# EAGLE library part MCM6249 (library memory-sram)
MEMORY
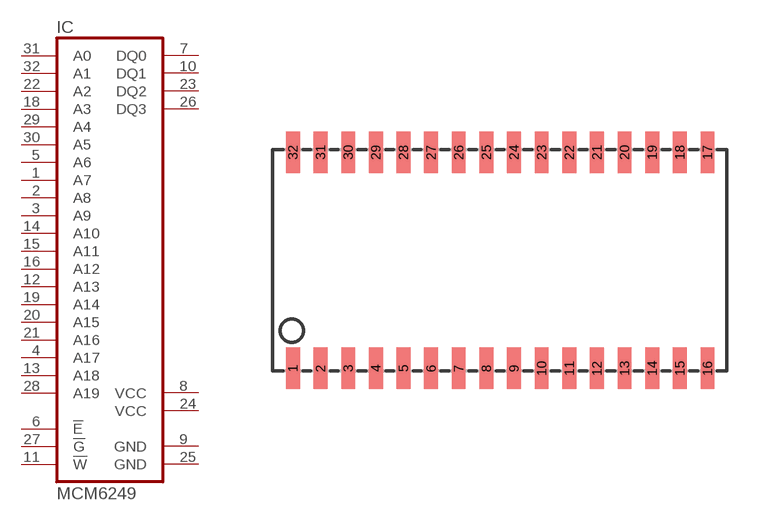
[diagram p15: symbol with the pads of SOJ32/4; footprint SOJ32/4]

Designator prefix IC

## MCM6249  [SOJ32/4]
1  A7  in
2  A8  in
3  A9  in
4  A17  in
5  A6  in
6  !E  in
7  DQ0
8  VCC  pwr
9  GND  pwr
10  DQ1
11  !W  in
12  A13  in
13  A18  in
14  A10  in
15  A11  in
16  A12  in
18  A3  in
19  A14  in
20  A15  in
21  A16  in
22  A2  in
23  DQ2
24  VCC  pwr
25  GND  pwr
26  DQ3
27  !G  in
28  A19  in
29  A4  in
30  A5  in
31  A0  in
32  A1  in

## Footprint SOJ32/4 (pad centres in mm)
Small Outline J-Bend
smd 0.635 x 1.905: 1 -9.525,-4.966; 2 -8.255,-4.966; 3 -6.985,-4.966; 4 -5.715,-4.966; 5 -4.445,-4.966; 6 -3.175,-4.966; 7 -1.905,-4.966; 8 -0.635,-4.966; 9 0.635,-4.966; 10 1.905,-4.966; 11 3.175,-4.966; 12 4.445,-4.966; 13 5.715,-4.966; 14 6.985,-4.966; 15 8.255,-4.966; 16 9.525,-4.966; 17 9.525,4.966; 18 8.255,4.966; 19 6.985,4.966; 20 5.715,4.966; 21 4.445,4.966; 22 3.175,4.966; 23 1.905,4.966; 24 0.635,4.966; 25 -0.635,4.966; 26 -1.905,4.966; 27 -3.175,4.966; 28 -4.445,4.966; 29 -5.715,4.966; 30 -6.985,4.966; 31 -8.255,4.966; 32 -9.525,4.966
